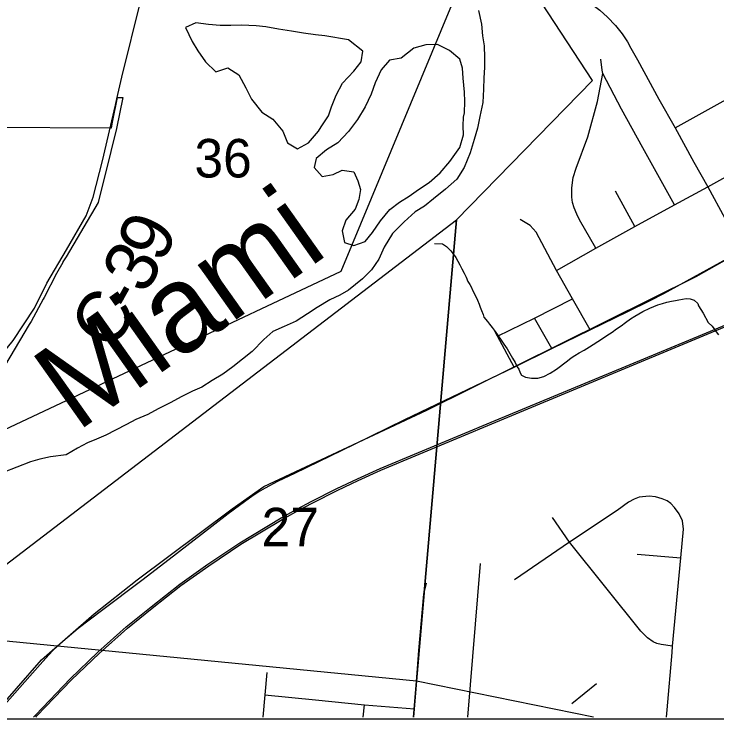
# Model space of a CAD drawing. Extents: x 0 to 34, y 0 to 22.
# Drawn here: x 5.042 to 5.806, y 14 to 14.766 of the extents above; entities that cross this region are included whole.
import ezdxf

# ---------------------------------------------------------------- set-up
doc = ezdxf.new("R2010")
doc.units = 0
for name, color, linetype in [('GM_X_City_Street', 7, 'Continuous'), ('GM_X_County_Road', 7, 'Continuous'), ('GM_X_County_Road_Text', 7, 'Continuous'), ('GM_X_Interchange_Ramps', 7, 'Continuous'), ('GM_X_Major_River', 7, 'Continuous'), ('GM_X_Major_River_Text', 7, 'Continuous'), ('GM_X_Minor_Lake', 7, 'Continuous'), ('GM_X_Minor_River', 7, 'Continuous'), ('GM_X_Rail_Line', 7, 'Continuous'), ('GM_X_Section', 7, 'Continuous'), ('GM_X_Section_Text', 7, 'Continuous'), ('GM_X_State_Shield', 7, 'Continuous'), ('GM_X_Township_Road', 7, 'Continuous'), ('SH_Data', 7, 'Continuous')]:
    doc.layers.add(name, color=color, linetype=linetype)

msp = doc.modelspace()

# ---------------------------------------------------------------- linework, layer by layer
at = {"layer": 'GM_X_City_Street'}
for p, q in [((5.71698, 14.53499), (5.69584, 14.57343)), ((5.62676, 14.40238), (5.60783, 14.43539)), ((5.71948, 14.17906), (5.76709, 14.17504)), ((5.53558, 14.00189), (5.54917, 14.16904)), ((5.64864, 14.01684), (5.67529, 14.03832)), ((5.42178, 14.00189), (5.42307, 14.01521))]:
    msp.add_line(p, q, dxfattribs=at)
for points in [[(5.76061, 14.64219), (5.82615, 14.67849), (5.89145, 14.71522), (5.95763, 14.75127), (6.02337, 14.78754), (6.08766, 14.8234), (6.15048, 14.85775), (6.22013, 14.89679), (6.34833, 14.96744), (6.44495, 15.02109), (6.46138, 15.0267)], [(5.63188, 14.48741), (5.67471, 14.51148), (5.71698, 14.53499), (5.75995, 14.55868), (5.79614, 14.57806), (5.86206, 14.61466), (5.92682, 14.65074), (5.99331, 14.68726), (6.05873, 14.72374), (6.12352, 14.75876), (6.1857, 14.79429), (6.25614, 14.83234), (6.32531, 14.87074)], [(5.75995, 14.55868), (5.72574, 14.62054), (5.70255, 14.66267), (5.68213, 14.70136), (5.68147, 14.70511), (5.67989, 14.71681)], [(5.67471, 14.51148), (5.65688, 14.54235), (5.65373, 14.54866), (5.65097, 14.55524), (5.64926, 14.56102), (5.64834, 14.56694), (5.64847, 14.57719), (5.64992, 14.58836), (5.65333, 14.59836), (5.66582, 14.63267), (5.67627, 14.67093), (5.68213, 14.70136)], [(5.66846, 14.42297), (5.64919, 14.4566), (5.63188, 14.48741), (5.60955, 14.52882), (5.60318, 14.53623), (5.59233, 14.54271)], [(5.56781, 14.416), (5.60783, 14.43539), (5.64919, 14.4566)], [(5.75133, 14.00189), (5.75211, 14.00975), (5.75743, 14.07228), (5.75792, 14.07897), (5.76709, 14.17504), (5.76993, 14.20636), (5.76863, 14.21521), (5.76504, 14.22277), (5.76013, 14.22967), (5.75589, 14.23392), (5.75191, 14.23697), (5.74673, 14.23923), (5.7393, 14.24122), (5.7324, 14.24188), (5.72165, 14.24109), (5.71608, 14.23896), (5.70998, 14.23551), (5.69757, 14.22647), (5.64601, 14.19199), (5.58627, 14.15101)], [(5.75792, 14.07897), (5.74538, 14.08075), (5.741, 14.08179), (5.73679, 14.0838), (5.7307, 14.08812), (5.72345, 14.09543), (5.64601, 14.19199), (5.62748, 14.21871)], [(5.47972, 14.04031), (5.48231, 14.07439), (5.48748, 14.13562), (5.49058, 14.14768)], [(5.31692, 14.05026), (5.3148, 14.02598), (5.31257, 14.00189)], [(5.47673, 14.00189), (5.47749, 14.0111), (5.47972, 14.04031)], [(5.3148, 14.02598), (5.36987, 14.02081), (5.42307, 14.01521), (5.47749, 14.0111)]]:
    msp.add_lwpolyline(points, dxfattribs=at)
at = {"layer": 'GM_X_County_Road'}
for points in [[(5.63106, 14.79548), (5.64007, 14.79214), (5.64709, 14.78949), (5.65709, 14.78453), (5.66759, 14.77834), (5.67875, 14.77015), (5.68717, 14.76271), (5.69577, 14.75354), (5.7031, 14.74455), (5.70883, 14.73581), (5.71273, 14.72879), (5.71975, 14.71613)], [(5.15395, 14.67387), (5.15938, 14.69728), (5.18008, 14.78081)], [(5.71975, 14.71613), (5.72677, 14.70348), (5.7432, 14.67357), (5.76061, 14.64219), (5.78114, 14.60509), (5.79614, 14.57806), (5.81493, 14.54418), (5.83475, 14.50977)], [(4.81728, 14.00189), (4.82536, 14.01985), (4.83523, 14.05343), (4.85248, 14.11153), (4.86683, 14.15868), (4.88246, 14.19555), (4.89752, 14.22408), (4.92886, 14.26783), (4.96261, 14.3176), (4.97823, 14.33701), (5.01328, 14.37725), (5.04136, 14.4112), (5.06454, 14.44639), (5.07806, 14.47344), (5.09936, 14.50982), (5.12068, 14.54657), (5.12836, 14.56691), (5.13835, 14.60658), (5.15237, 14.66704), (5.15395, 14.67387)], [(5.30738, 14.24623), (5.31542, 14.25101), (5.32902, 14.25824), (5.34731, 14.26706), (5.41236, 14.29852), (5.46682, 14.32523), (5.52665, 14.35403), (5.58584, 14.38218), (5.62676, 14.40238), (5.66846, 14.42297), (5.70936, 14.44277), (5.7337, 14.45468), (5.74848, 14.46222), (5.83475, 14.50977), (5.89986, 14.54569), (5.94604, 14.5714)], [(5.02044, 14.00189), (5.03226, 14.01565), (5.05956, 14.04649), (5.07348, 14.06223), (5.08419, 14.07398), (5.09517, 14.08464), (5.11213, 14.09861), (5.13737, 14.11771), (5.18106, 14.15077), (5.21103, 14.17341), (5.25727, 14.20934), (5.27502, 14.22305), (5.29267, 14.23623), (5.30202, 14.24304), (5.30738, 14.24623)]]:
    msp.add_lwpolyline(points, dxfattribs=at)
at = {"layer": 'GM_X_Interchange_Ramps'}
msp.add_lwpolyline([(5.01517, 14.64318), (5.14726, 14.64214), (5.14802, 14.64213), (5.14929, 14.64831), (5.15483, 14.67523), (5.15774, 14.67518), (5.16049, 14.67513), (5.16063, 14.67513), (5.15371, 14.64149), (5.14759, 14.61675), (5.13382, 14.56111), (5.09873, 14.50225), (5.09543, 14.49658), (5.09514, 14.4961), (5.08838, 14.48417), (5.07491, 14.45788), (5.07404, 14.45629), (5.0608, 14.43202), (5.05879, 14.42864), (5.02709, 14.37524)], dxfattribs=at)
at = {"layer": 'GM_X_Major_River'}
for points in [[(5.54716, 14.76967), (5.55028, 14.75478), (5.55155, 14.74221), (5.55323, 14.73153), (5.55373, 14.7186), (5.55351, 14.70796), (5.5529, 14.69656), (5.55265, 14.6844), (5.55159, 14.66998), (5.54861, 14.65445), (5.54607, 14.64195), (5.54239, 14.62948), (5.53791, 14.61512), (5.53149, 14.59929), (5.52362, 14.58651), (5.51122, 14.57573), (5.49806, 14.56497), (5.48838, 14.55718), (5.47836, 14.55091), (5.46634, 14.54012), (5.45352, 14.52745), (5.44446, 14.5128), (5.43886, 14.49961), (5.43063, 14.48799), (5.42092, 14.4783), (5.40582, 14.46605)], [(5.40582, 14.46605), (5.39619, 14.46054), (5.38543, 14.45543), (5.37155, 14.44696), (5.36114, 14.44032), (5.34879, 14.4322), (5.33573, 14.42637), (5.32344, 14.42091), (5.31374, 14.41236), (5.30092, 14.39931), (5.29046, 14.39077), (5.28002, 14.38262), (5.26919, 14.37447), (5.25764, 14.36786), (5.24645, 14.36047), (5.23608, 14.35612), (5.22454, 14.35026), (5.21184, 14.34329), (5.19877, 14.33709), (5.1876, 14.33084), (5.17455, 14.3254), (5.16454, 14.31989), (5.15261, 14.31367), (5.14184, 14.30818), (5.13185, 14.30381), (5.12226, 14.29982), (5.1111, 14.29434), (5.09877, 14.28698), (5.08198, 14.28465), (5.07013, 14.28222), (5.06017, 14.27937), (5.04521, 14.27359), (5.03062, 14.26779)]]:
    msp.add_lwpolyline(points, dxfattribs=at)
at = {"layer": 'GM_X_Minor_Lake'}
for points in [[(5.40566, 14.73785), (5.37987, 14.74216), (5.36999, 14.74349), (5.35671, 14.74527), (5.34381, 14.74743), (5.32977, 14.74961), (5.31574, 14.75216), (5.30548, 14.75312), (5.28951, 14.75382), (5.2777, 14.75367), (5.26628, 14.75351), (5.25374, 14.75452), (5.23969, 14.75632), (5.22855, 14.75121), (5.23585, 14.73624), (5.24211, 14.72586), (5.25024, 14.71391), (5.26144, 14.70305), (5.27447, 14.70735), (5.2865, 14.69989), (5.2942, 14.68567), (5.30042, 14.67339), (5.31156, 14.65948), (5.32358, 14.65164), (5.33435, 14.63851), (5.33942, 14.62586), (5.35033, 14.61957), (5.36227, 14.62617), (5.37318, 14.63851)], [(5.37318, 14.63851), (5.37594, 14.64339), (5.38418, 14.6554), (5.38743, 14.66522), (5.39225, 14.67766), (5.39937, 14.69083), (5.41144, 14.7039), (5.41964, 14.71401), (5.4214, 14.72576), (5.40566, 14.73785)], [(5.48968, 14.7324), (5.47666, 14.72885), (5.46312, 14.71809), (5.45013, 14.71569), (5.44116, 14.70522), (5.43478, 14.69128), (5.43034, 14.67882), (5.42397, 14.66526), (5.4157, 14.65136), (5.40591, 14.63824), (5.39424, 14.62593), (5.38191, 14.61856), (5.37067, 14.6089), (5.36857, 14.59906), (5.37713, 14.58939), (5.38897, 14.59144), (5.39896, 14.59618), (5.41149, 14.59442), (5.41586, 14.58483), (5.41871, 14.57527), (5.41696, 14.56428), (5.41295, 14.55409), (5.40281, 14.54213), (5.39876, 14.53043), (5.40155, 14.51783), (5.41138, 14.51459), (5.42403, 14.51891), (5.43184, 14.52864), (5.44048, 14.54139), (5.45063, 14.55373), (5.46106, 14.56151), (5.47186, 14.56814), (5.4819, 14.57517), (5.49348, 14.58292), (5.50549, 14.59333), (5.51602, 14.60567), (5.52661, 14.62105), (5.5307, 14.63465), (5.53052, 14.64454), (5.53071, 14.65404)], [(5.53071, 14.65404), (5.53195, 14.65858), (5.53219, 14.67074), (5.53164, 14.68101), (5.53043, 14.69624), (5.52952, 14.70729), (5.52667, 14.71685), (5.51544, 14.72619), (5.50263, 14.73291), (5.48968, 14.7324)]]:
    msp.add_lwpolyline(points, dxfattribs=at)
at = {"layer": 'GM_X_Minor_River'}
msp.add_lwpolyline([(5.49935, 14.51667), (5.50778, 14.51611), (5.51229, 14.51333), (5.51712, 14.50865), (5.52043, 14.50399), (5.52227, 14.50128), (5.52664, 14.49356), (5.52881, 14.48894), (5.53136, 14.48431), (5.53353, 14.48006), (5.53532, 14.47545), (5.53752, 14.47197), (5.53934, 14.46888), (5.54041, 14.46581), (5.5426, 14.46195), (5.54585, 14.45501), (5.54765, 14.45078), (5.5487, 14.44732), (5.55014, 14.44386), (5.55193, 14.43963), (5.55299, 14.43656), (5.55669, 14.4319), (5.55889, 14.4288), (5.56185, 14.4253), (5.56517, 14.42103), (5.56849, 14.41638), (5.5718, 14.41173), (5.57473, 14.40709), (5.57802, 14.40206), (5.58387, 14.39201), (5.5868, 14.38737), (5.58896, 14.38275), (5.5908, 14.38004), (5.59223, 14.3762), (5.59368, 14.3735), (5.5982, 14.37148), (5.60465, 14.37018), (5.61152, 14.3704), (5.61804, 14.37214), (5.625, 14.37578), (5.63197, 14.38018), (5.64364, 14.38904), (5.64792, 14.39236), (5.6518, 14.39494), (5.65645, 14.39787), (5.66186, 14.40079), (5.66767, 14.40445), (5.68084, 14.41251), (5.68666, 14.41656), (5.69247, 14.42023), (5.69714, 14.42392), (5.70219, 14.42723), (5.70686, 14.43092), (5.71229, 14.4346), (5.71694, 14.43753), (5.72546, 14.44266), (5.73317, 14.44628), (5.73742, 14.44808), (5.74204, 14.44987), (5.74703, 14.45127), (5.75164, 14.45269), (5.75663, 14.45409), (5.76122, 14.45474), (5.76467, 14.45542), (5.76888, 14.45608), (5.77271, 14.45675), (5.7769, 14.45664), (5.78143, 14.45501), (5.78553, 14.45148), (5.78623, 14.4488), (5.79136, 14.44106), (5.79681, 14.43064), (5.8009, 14.42674), (5.80532, 14.42054), (5.80791, 14.41743)], dxfattribs=at)
at = {"layer": 'GM_X_Rail_Line'}
for points in [[(5.01732, 14.00189), (5.07199, 14.06435), (5.12947, 14.11429), (5.176, 14.15127), (5.27919, 14.22824), (5.31365, 14.25269), (5.49073, 14.33558), (5.78364, 14.48073), (6.17515, 14.70175), (6.29306, 14.76767), (6.5502, 14.90974), (6.59183, 14.93964), (6.85985, 15.08152), (6.90635, 15.10076), (7.03045, 15.16419), (7.12702, 15.2232), (7.27714, 15.32361), (7.37171, 15.41695), (7.56811, 15.60595)], [(5.06333, 14.00189), (5.06578, 14.00455), (5.10333, 14.04368), (5.13337, 14.07245), (5.16414, 14.09995), (5.19116, 14.12191), (5.22253, 14.14638), (5.25288, 14.16806), (5.28768, 14.19133), (5.33252, 14.21841), (5.35019, 14.22825), (5.3652, 14.23607), (5.39323, 14.25035), (5.41544, 14.26093), (5.44009, 14.27214), (5.565, 14.32428), (5.79039, 14.41785), (6.05395, 14.52735)], [(5.06593, 14.00189), (5.06718, 14.00325), (5.10469, 14.04234), (5.13467, 14.07105), (5.16539, 14.0985), (5.19236, 14.12042), (5.22368, 14.14486), (5.25397, 14.1665), (5.28871, 14.18972), (5.33349, 14.21676), (5.3511, 14.22657), (5.36609, 14.23438), (5.39408, 14.24864), (5.41625, 14.2592), (5.44086, 14.27039), (5.56573, 14.32252), (5.79112, 14.41609), (6.05469, 14.52559)]]:
    msp.add_lwpolyline(points, dxfattribs=at)
at = {"layer": 'GM_X_Section'}
msp.add_lwpolyline([(5.67203, 14.00189), (5.47973, 14.04108), (5.52313, 14.54242), (5.67085, 14.69361), (5.55401, 14.87283), (5.56525, 15.05515), (6.67904, 14.83565), (6.60811, 14.00189)], dxfattribs=at)
for points in [[(5.01738, 14.78059), (5.51759, 14.77547), (5.3974, 14.48625), (5.01237, 14.30498)], [(4.93655, 14.09403), (5.52313, 14.54242), (5.47973, 14.04108)]]:
    msp.add_lwpolyline(points, close=True, dxfattribs=at)
at = {"layer": 'GM_X_State_Shield'}
for points in [[(5.47624, 14.00189), (5.47973, 14.04108), (4.93655, 14.09403), (4.86976, 14.00189)], [(5.67203, 14.00189), (5.47973, 14.04108), (5.47624, 14.00189)]]:
    msp.add_lwpolyline(points, dxfattribs=at)
at = {"layer": 'GM_X_Township_Road'}
msp.add_lwpolyline([(5.58584, 14.38218), (5.56781, 14.416), (5.56448, 14.42199)], dxfattribs=at)
at = {"layer": 'SH_Data'}
msp.add_line((2, 14), (9, 14), dxfattribs=at)

# ---------------------------------------------------------------- texts
at = {"layer": 'GM_X_County_Road_Text'}
for s, rotation, p in [('9', 64.5975, (5.20323, 14.49361)), ('3', 61.51722, (5.18503, 14.45988)), ('-', 60.7007, (5.17318, 14.43876)), ('C', 60.48555, (5.15008, 14.39795))]:
    msp.add_text(s, height=0.05682, rotation=rotation, dxfattribs=at).set_placement(p)
at = {"layer": 'GM_X_Major_River_Text'}
msp.add_text('Miami', height=0.094697, rotation=35.31809, dxfattribs=at).set_placement((5.11035, 14.31094))
at = {"layer": 'GM_X_Section_Text'}
for s, p in [('36', (5.23835, 14.58834)), ('27', (5.31127, 14.18751))]:
    msp.add_text(s, height=0.041856, rotation=0.00001, dxfattribs=at).set_placement(p)

doc.saveas('drawing.dxf')
